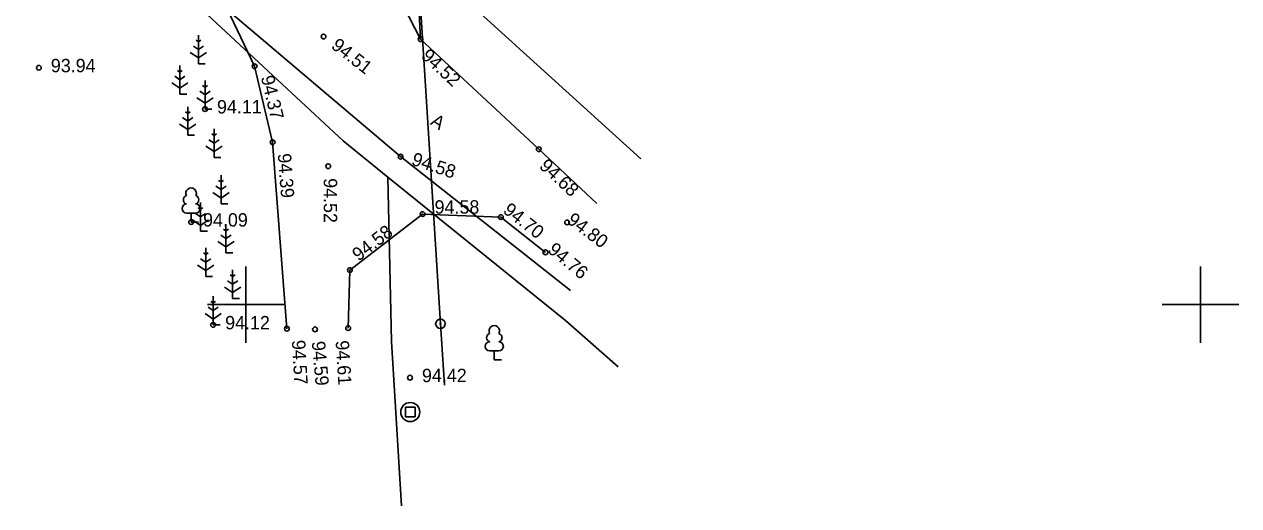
# Model space of a CAD drawing. Extents: x 648748 to 649126, y 6457789 to 6458252.
# Drawn here: x 648938.4 to 649002, y 6457789.5 to 6457814.7 of the extents above; entities that cross this region are included whole.
import ezdxf

# ---------------------------------------------------------------- set-up
doc = ezdxf.new("R2010")
doc.units = 0
for name, color, linetype in [('DKAEV', 7, 'Continuous'), ('HALJASTUS', 7, 'Continuous'), ('KORGUS-EH2000', 7, 'Continuous'), ('MPOHULIIN', 7, 'Continuous'), ('PIIR', 7, 'Continuous'), ('POST', 7, 'Continuous'), ('PUU', 7, 'Continuous'), ('SITRASS', 7, 'Continuous'), ('TEE', 7, 'Continuous'), ('VORK', 7, 'Continuous')]:
    doc.layers.add(name, color=color, linetype=linetype)

msp = doc.modelspace()

# ---------------------------------------------------------------- linework, layer by layer
at = {"layer": 'DKAEV'}
for p, q in [((648958.367, 6457794.12), (648958.367, 6457794.62)), ((648958.367, 6457794.62), (648958.867, 6457794.62)), ((648958.867, 6457794.62), (648958.867, 6457794.12)), ((648958.867, 6457794.12), (648958.367, 6457794.12))]:
    msp.add_line(p, q, dxfattribs=at)
msp.add_circle((648958.617, 6457794.37), 0.5, dxfattribs=at)
at = {"layer": 'HALJASTUS'}
msp.add_lwpolyline([(648959.157, 6457813.907), (648957.16, 6457853.059), (648954.425, 6457897.359), (648954.612, 6457901.996)], dxfattribs=at)
at = {"layer": 'KORGUS-EH2000'}
for centre in [(648954.077, 6457814.047), (648959.157, 6457813.907), (648939.168, 6457812.41), (648950.466, 6457812.488), (648947.868, 6457810.249), (648951.409, 6457808.506), (648965.346, 6457808.142), (648954.322, 6457807.252), (648958.111, 6457807.754), (648959.264, 6457804.743), (648947.14, 6457804.323), (648963.359, 6457804.586), (648966.831, 6457804.307), (648965.699, 6457802.739), (648955.458, 6457801.807), (648948.296, 6457798.937), (648952.157, 6457798.739), (648953.63, 6457798.703), (648955.364, 6457798.772), (648958.602, 6457796.17)]:
    msp.add_circle(centre, 0.125, dxfattribs=at)
at = {"layer": 'MPOHULIIN'}
for points in [[(648956.812, 6457852.771), (648960.195, 6457798.998)], [(648960.195, 6457798.998), (648960.405, 6457795.777)]]:
    msp.add_lwpolyline(points, dxfattribs=at)
at = {"layer": 'PIIR'}
for p, q in [((648942.8, 6457820.04), (648955.1, 6457808.59)), ((648970.699, 6457807.634), (648958.86, 6457818.39)), ((648955.1, 6457808.59), (648957.45, 6457806.68)), ((648957.45, 6457806.68), (648957.63, 6457798.06)), ((648966.74, 6457799.16), (648957.45, 6457806.68)), ((648969.5, 6457796.747), (648966.74, 6457799.16)), ((648957.63, 6457798.06), (648958.154, 6457789.461))]:
    msp.add_line(p, q, dxfattribs=at)
at = {"layer": 'POST'}
for radius in [0.25, 0.0234]:
    msp.add_circle((648960.195, 6457798.998), radius, dxfattribs=at)
at = {"layer": 'PUU'}
for p, q in [((648947.523, 6457813.767), (648947.399, 6457813.85)), ((648947.523, 6457814.117), (648947.523, 6457812.617)), ((648947.648, 6457813.85), (648947.523, 6457813.767)), ((648947.099, 6457813.207), (648947.523, 6457812.924)), ((648947.523, 6457813.367), (648947.257, 6457813.545)), ((648947.79, 6457813.545), (648947.523, 6457813.367)), ((648947.523, 6457812.924), (648947.948, 6457813.207)), ((648946.549, 6457812.536), (648946.549, 6457811.036)), ((648947.883, 6457812.617), (648947.523, 6457812.617)), ((648946.549, 6457811.786), (648946.283, 6457811.964)), ((648946.549, 6457812.186), (648946.425, 6457812.269)), ((648946.674, 6457812.269), (648946.549, 6457812.186)), ((648946.816, 6457811.964), (648946.549, 6457811.786)), ((648947.868, 6457811.749), (648947.868, 6457810.249)), ((648946.125, 6457811.626), (648946.549, 6457811.343)), ((648946.549, 6457811.343), (648946.974, 6457811.626)), ((648947.868, 6457810.999), (648947.602, 6457811.177)), ((648947.868, 6457811.399), (648947.744, 6457811.482)), ((648947.993, 6457811.482), (648947.868, 6457811.399)), ((648948.135, 6457811.177), (648947.868, 6457810.999)), ((648946.909, 6457811.036), (648946.549, 6457811.036)), ((648947.444, 6457810.839), (648947.868, 6457810.556)), ((648947.868, 6457810.556), (648948.293, 6457810.839)), ((648946.962, 6457810.021), (648946.838, 6457810.104)), ((648946.962, 6457810.371), (648946.962, 6457808.871)), ((648947.087, 6457810.104), (648946.962, 6457810.021)), ((648948.228, 6457810.249), (648947.868, 6457810.249)), ((648946.538, 6457809.461), (648946.962, 6457809.178)), ((648946.962, 6457809.621), (648946.696, 6457809.799)), ((648947.229, 6457809.799), (648946.962, 6457809.621)), ((648946.962, 6457809.178), (648947.387, 6457809.461)), ((648948.342, 6457809.215), (648948.342, 6457807.715)), ((648947.322, 6457808.871), (648946.962, 6457808.871)), ((648948.342, 6457808.465), (648948.076, 6457808.643)), ((648948.342, 6457808.865), (648948.218, 6457808.948)), ((648948.467, 6457808.948), (648948.342, 6457808.865)), ((648948.609, 6457808.643), (648948.342, 6457808.465)), ((648947.918, 6457808.305), (648948.342, 6457808.022)), ((648948.342, 6457808.022), (648948.767, 6457808.305)), ((648948.702, 6457807.715), (648948.342, 6457807.715)), ((648948.706, 6457806.777), (648948.706, 6457805.277)), ((648948.706, 6457806.027), (648948.44, 6457806.205)), ((648948.706, 6457806.427), (648948.582, 6457806.51)), ((648948.831, 6457806.51), (648948.706, 6457806.427)), ((648948.973, 6457806.205), (648948.706, 6457806.027)), ((648948.282, 6457805.867), (648948.706, 6457805.584)), ((648948.706, 6457805.584), (648949.131, 6457805.867)), ((648947.38, 6457804.798), (648946.9, 6457804.798)), ((648947.14, 6457804.323), (648947.14, 6457804.798)), ((648947.634, 6457804.595), (648947.368, 6457804.773)), ((648947.634, 6457804.995), (648947.51, 6457805.078)), ((648947.634, 6457805.345), (648947.634, 6457803.845)), ((648947.759, 6457805.078), (648947.634, 6457804.995)), ((648947.901, 6457804.773), (648947.634, 6457804.595)), ((648949.066, 6457805.277), (648948.706, 6457805.277)), ((648947.52, 6457804.323), (648947.14, 6457804.323)), ((648947.21, 6457804.435), (648947.634, 6457804.152)), ((648947.634, 6457804.152), (648948.059, 6457804.435)), ((648948.967, 6457804.214), (648948.967, 6457802.714)), ((648947.994, 6457803.845), (648947.634, 6457803.845)), ((648948.967, 6457803.464), (648948.701, 6457803.642)), ((648948.967, 6457803.864), (648948.843, 6457803.947)), ((648949.092, 6457803.947), (648948.967, 6457803.864)), ((648949.234, 6457803.642), (648948.967, 6457803.464)), ((648947.906, 6457802.972), (648947.906, 6457801.472)), ((648948.543, 6457803.304), (648948.967, 6457803.021)), ((648948.967, 6457803.021), (648949.392, 6457803.304)), ((648947.906, 6457802.222), (648947.64, 6457802.4)), ((648947.906, 6457802.622), (648947.782, 6457802.705)), ((648948.031, 6457802.705), (648947.906, 6457802.622)), ((648948.173, 6457802.4), (648947.906, 6457802.222)), ((648949.327, 6457802.714), (648948.967, 6457802.714)), ((648947.482, 6457802.062), (648947.906, 6457801.779)), ((648947.906, 6457801.779), (648948.331, 6457802.062)), ((648949.316, 6457801.821), (648949.316, 6457800.321)), ((648948.266, 6457801.472), (648947.906, 6457801.472)), ((648949.316, 6457801.071), (648949.05, 6457801.249)), ((648949.316, 6457801.471), (648949.192, 6457801.554)), ((648949.441, 6457801.554), (648949.316, 6457801.471)), ((648949.583, 6457801.249), (648949.316, 6457801.071)), ((648948.296, 6457800.437), (648948.296, 6457798.937)), ((648948.892, 6457800.911), (648949.316, 6457800.628)), ((648949.316, 6457800.628), (648949.741, 6457800.911)), ((648949.676, 6457800.321), (648949.316, 6457800.321)), ((648948.296, 6457799.687), (648948.03, 6457799.865)), ((648948.296, 6457800.087), (648948.172, 6457800.17)), ((648948.421, 6457800.17), (648948.296, 6457800.087)), ((648948.563, 6457799.865), (648948.296, 6457799.687)), ((648947.872, 6457799.527), (648948.296, 6457799.244)), ((648948.296, 6457799.244), (648948.721, 6457799.527)), ((648948.656, 6457798.937), (648948.296, 6457798.937)), ((648963.256, 6457797.575), (648962.776, 6457797.575)), ((648963.016, 6457797.1), (648963.016, 6457797.575)), ((648963.396, 6457797.1), (648963.016, 6457797.1))]:
    msp.add_line(p, q, dxfattribs=at)
for centre, radius, start, end in [((648947.14, 6457805.843), 0.277, 332.58, 207.42), ((648946.97, 6457805.496), 0.233, 109.022, 253.142), ((648947.31, 6457805.496), 0.233, 286.851, 70.986), ((648946.903, 6457805.036), 0.238, 90.002, 269.395), ((648947.378, 6457805.036), 0.238, 270.605, 89.998), ((648962.846, 6457798.272), 0.233, 109.022, 253.142), ((648963.016, 6457798.62), 0.277, 332.58, 207.42), ((648963.186, 6457798.272), 0.233, 286.851, 70.986), ((648962.778, 6457797.812), 0.238, 90.002, 269.395), ((648963.253, 6457797.812), 0.238, 270.605, 89.998)]:
    msp.add_arc(centre, radius, start, end, dxfattribs=at)
at = {"layer": 'SITRASS'}
msp.add_lwpolyline([(648938.405, 6457825.832), (648941.1, 6457823.277), (648948.868, 6457815.581), (648958.111, 6457807.754), (648963.697, 6457803.355), (648967.011, 6457800.731)], dxfattribs=at)
at = {"layer": 'TEE'}
for points in [[(648968.389, 6457805.307), (648965.346, 6457808.142), (648959.157, 6457813.907), (648956.21, 6457819.654), (648955.582, 6457823.407), (648955.385, 6457829.76), (648955.069, 6457837.324), (648954.599, 6457843.909), (648954.508, 6457846.214), (648953.429, 6457857.012), (648952.328, 6457868.633), (648951.152, 6457880.117), (648950.078, 6457892.426), (648948.684, 6457906.84), (648947.93, 6457917.625), (648947.533, 6457928.443), (648947.533, 6457936.934), (648947.619, 6457941.404), (648947.623, 6457950.601)], [(648952.157, 6457798.739), (648951.409, 6457808.506), (648950.466, 6457812.488), (648947.955, 6457817.789), (648943.757, 6457822.758), (648939.744, 6457826.502), (648938.528, 6457827.562)], [(648965.699, 6457802.739), (648963.359, 6457804.586), (648959.264, 6457804.743), (648955.458, 6457801.807), (648955.364, 6457798.772)]]:
    msp.add_lwpolyline(points, dxfattribs=at)
at = {"layer": 'VORK'}
for p, q in [((648950, 6457802), (648950, 6457798)), ((649000, 6457802), (649000, 6457798)), ((648948, 6457800), (648952, 6457800)), ((648998, 6457800), (649002, 6457800))]:
    msp.add_line(p, q, dxfattribs=at)

# ---------------------------------------------------------------- texts
at = {"layer": 'KORGUS-EH2000'}
for s, rotation, p in [(' 94.51', 321.93182, (648954.222, 6457813.637)), (' 94.52', 317.02999, (648958.948, 6457813.145)), (' 94.37', 283.33485, (648950.73, 6457812.173)), (' 94.58', 341.59363, (648958.386, 6457807.417)), (' 94.39', 274.37927, (648951.654, 6457808.157)), (' 94.68', 317.02999, (648965.137, 6457807.379)), (' 94.52', 270, (648954.088, 6457806.885)), (' 94.70', 321.72235, (648963.221, 6457805.013)), (' 94.80', 323.0665, (648966.556, 6457804.478)), (' 94.58', 37.64523, (648955.708, 6457802.084)), (' 94.76', 320.03676, (648965.564, 6457802.954)), (' 94.57', 273.3875, (648952.4, 6457798.386)), (' 94.59', 275.24925, (648953.431, 6457798.316)), (' 94.61', 273.65801, (648954.689, 6457798.361))]:
    msp.add_text(s, height=0.7, rotation=rotation, dxfattribs=at).set_placement(p)
for s, p in [(' 93.94', (648939.535, 6457812.177)), (' 94.11', (648948.235, 6457810.016)), (' 94.58', (648959.631, 6457804.766)), (' 94.09', (648947.507, 6457804.09)), (' 94.12', (648948.663, 6457798.704)), (' 94.42', (648958.969, 6457795.937))]:
    msp.add_text(s, height=0.7, dxfattribs=at).set_placement(p)
at = {"layer": 'TEE'}
msp.add_text('A', height=0.7, rotation=327.05193, dxfattribs=at).set_placement((648959.622, 6457809.465))

doc.saveas('drawing.dxf')
